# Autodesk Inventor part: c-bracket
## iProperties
Author: Elise Moss
Created: 2001-09
Part Number: c-bracket
Document SubType Name: Modeling
Designer: Elise Moss
Control State: 0
Master: False
Checked Out: False
PropertySet Name: Design Tracking Control
Length Units: 11272
Angle Units: 11279
Time Units: 11290
Mass Units: 11286
Shininess: 3
Angle Display Precision: 2
Document Length Units: 11272
Document Angle Units: 11286
Document Time Units: 11279
Document Mass Units: 11290
Document Length Units Precision: 3
Document Angle Units Precision: 0
Compacted: False
PropertySet Name: _Private Model Information
Density: 0.0
Volumn: 0.0
Area: 0.0
PropertySet Name: Model Information
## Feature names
1. Extrusion1
2. Extrusion2
3. Extrusion3
4. Extrusion4
5. Extrusion5
6. Extrusion6
7. Mirror1
8. Fillet1
9. Hole1
